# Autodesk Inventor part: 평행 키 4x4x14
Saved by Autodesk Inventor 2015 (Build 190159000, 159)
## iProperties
Created: 2024-12
Part Number: 평행 키 4x4x14
Material: 일반
Document SubType Name: Modeling
Designer: 102-5
Density: 1 g/cm^3
Appearance: 기본값
Author: 102-5
Author: jhkim
Description: 키 및 해당 키홈
Creation Date: 2024-12-12
Sending System: Autodesk Inventor 2025
Preprocessor: ST-DEVELOPER v20
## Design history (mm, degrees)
node "평행 키 4x4x141"
body "Solid1"
node "기준1"
